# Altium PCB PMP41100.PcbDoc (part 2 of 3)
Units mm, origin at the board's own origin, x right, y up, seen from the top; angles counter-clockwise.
Board outline 49.66 x 37.36 mm, 2 copper layers (Top Layer, Bottom Layer), stack 1.016 mm thick; 100 components, 64 nets, 348 pads, 1132 vias.
Unrouted connection lines stored in the file: 60.
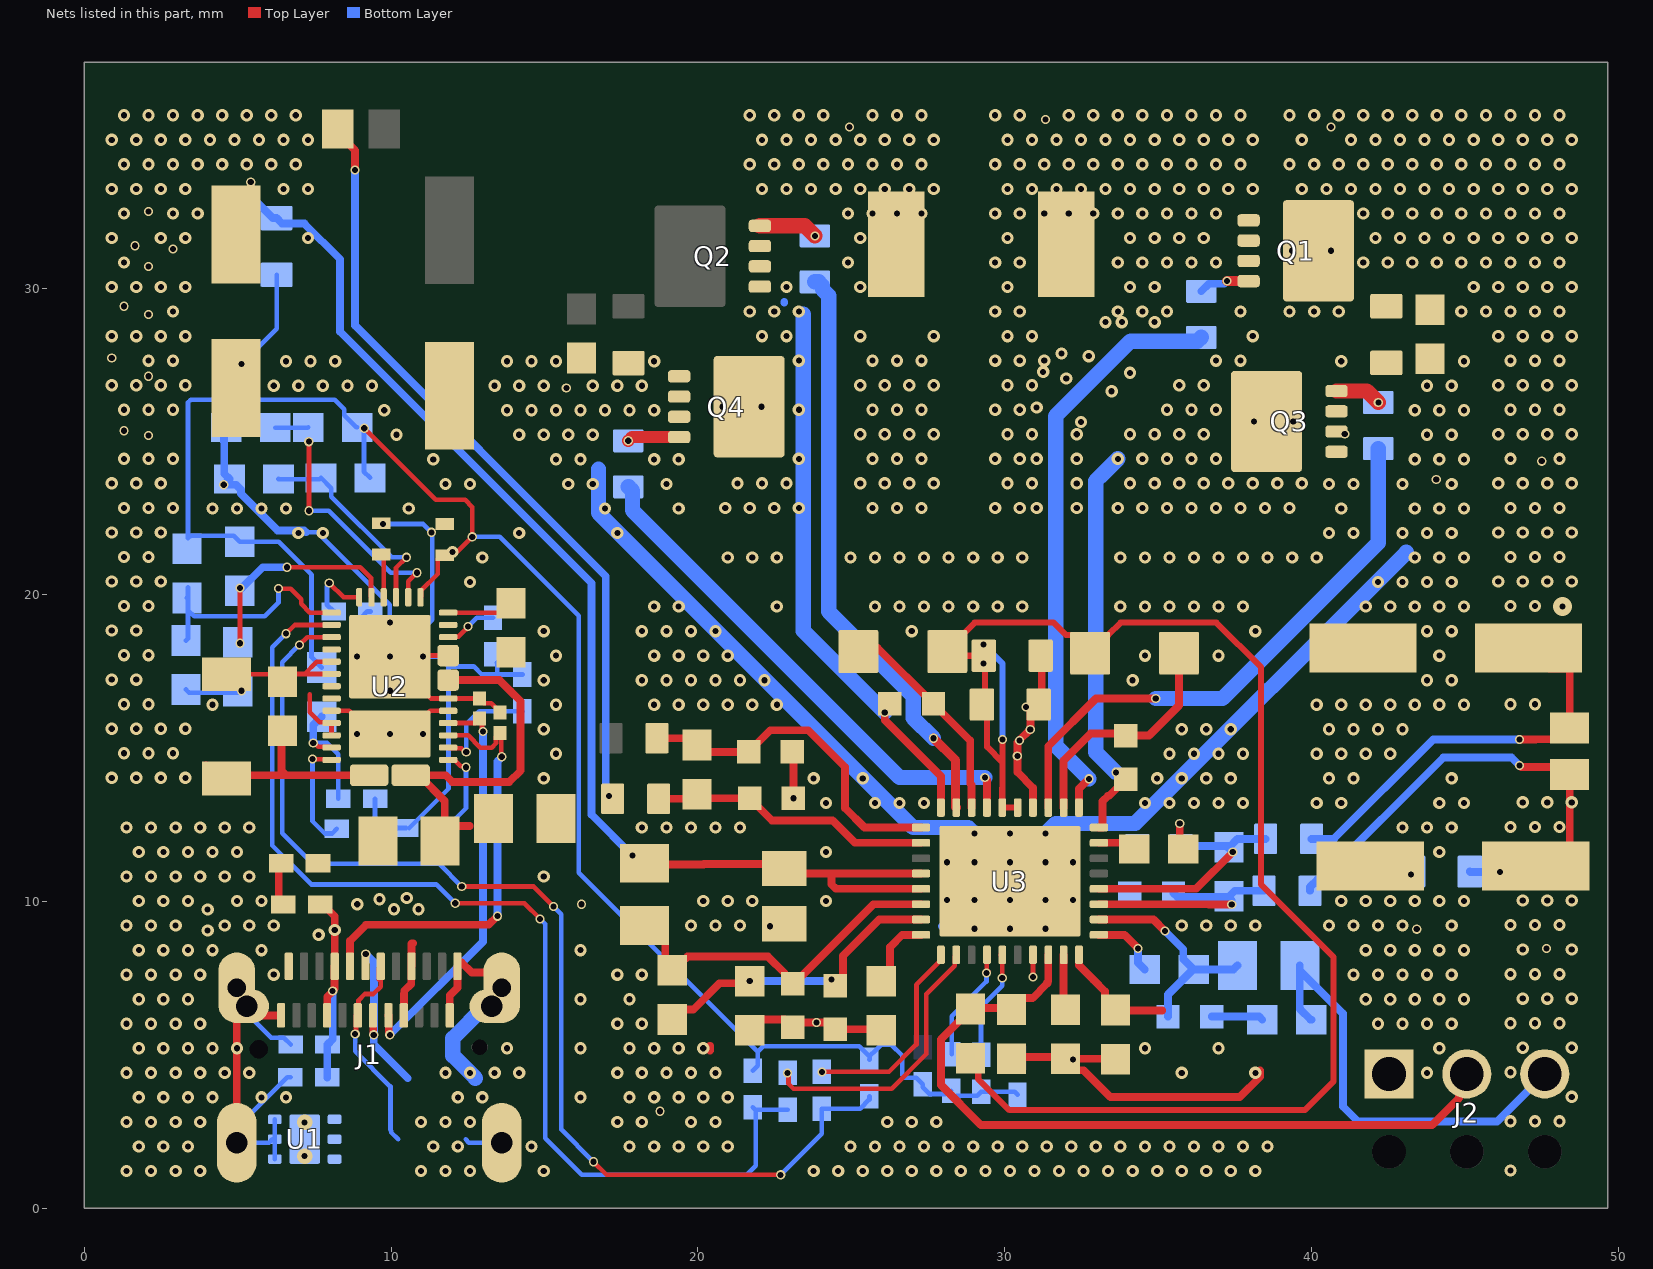
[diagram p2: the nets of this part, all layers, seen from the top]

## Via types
v1: diameter 0.4, hole 0.2, Top Layer to Bottom Layer, 988 vias
v2: diameter 0.3, hole 0.2, Top Layer to Bottom Layer, tented both sides, 103 vias
v3: diameter 0.5, hole 0.2, Top Layer to Bottom Layer, 34 vias
v4: diameter 0.4, hole 0.2, Top Layer to Bottom Layer, tented both sides, 5 vias
v5: diameter 0.4, hole 0.203, Top Layer to Bottom Layer, tented both sides, 1 vias
v6: diameter 0.61, hole 0.203, Top Layer to Bottom Layer, tented both sides, 1 vias

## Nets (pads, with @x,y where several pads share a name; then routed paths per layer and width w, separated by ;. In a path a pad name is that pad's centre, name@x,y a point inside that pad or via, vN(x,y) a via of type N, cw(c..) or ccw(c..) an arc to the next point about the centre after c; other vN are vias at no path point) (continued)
ACN: C13.2 C16.1 R21.1 U3.29 | length 11.2
  Top Layer w0.254: R21.1@18.666,15.327 19.748,15.327 C13.2@19.97,15.105 20.194,14.881 C16.1@21.655,14.881 22.363,15.589 23.594,15.589 24.799,14.383 24.799,13.047 25.43,12.416 U3.29@27.274,12.416
ACOV: C22.1 R31.1 R32.2 U3.35 | length 10.2
  Top Layer w0.254: R31.1@19.162,6.158 19.482,6.478 19.848,6.478 20.706,7.336 21.616,7.336 v2(21.689,7.409) ; v2(24.351,7.457) C22.1@24.351,7.386 ; C22.1@24.479,7.259 C22.1@24.351,7.386 ; U3.35@27.274,9.416 25.911,9.416 24.733,8.238 24.733,7.513 24.606,7.386 C22.1@24.351,7.386
  Bottom Layer w0.254: v2(21.689,7.409) 24.29,7.409 24.339,7.457 v2(24.351,7.457)
ACP: C13.1 C15.1 R20.1 U3.30 | length 9.3
  Top Layer w0.254: R20.1@18.721,13.35 19.815,13.35 C13.1@19.97,13.505 20.105,13.369 C15.1@21.691,13.369 22.412,12.648 24.39,12.648 25.123,11.916 U3.30@27.274,11.916
ACUV: C19.1 R30.1 R31.2 U3.34 | length 13.6
  Top Layer w0.254: R30.1@17.758,8.71 18.149,9.1 R30.1@18.378,9.1 ; U3.34@27.274,9.916 25.724,9.916 23.383,7.575 23.341,7.575 C19.1@23.087,7.321 22.833,7.575 22.833,7.659 22.287,8.206 19.659,8.206 19.584,8.131 19.51,8.131 19.162,7.783 R31.2@19.162,7.758 18.959,7.758 18.933,7.732 R30.1@18.933,8.71 ; R30.1@18.378,9.1 18.543,9.1 R30.1@18.933,8.71 ; R30.1@18.378,9.1 R30.1@18.26,9.218 18.768,8.71 R30.1@18.933,8.71
ADCIN1: R1.1 R5.2 U2.2 | length 8.6
  Top Layer w0.152: v2(7.316,24.994) 7.32,24.99 7.32,22.745 v2(7.324,22.741) ; U2.2@10.557,19.921 10.557,20.437 v2(10.841,20.721)
  Bottom Layer w0.152: R5.2@6.224,25.451 7.282,25.451 R1.1@7.293,25.462 ; v2(7.324,22.741) 7.967,22.741 9.987,20.721 v2(10.841,20.721)
ADCIN2: R2.1 R7.2 U2.3 | length 6.9
  Top Layer w0.152: U2.3@10.157,19.921 10.157,20.879 v2(10.501,21.223)
  Bottom Layer w0.152: R7.2@6.33,23.777 6.34,23.767 7.664,23.767 R2.1@7.712,23.815 8.051,23.476 8.051,23.2 10.028,21.223 v2(10.501,21.223)
ADCIN3: R3.1 R6.2 U2.5 | length 7.1
  Top Layer w0.152: v2(5.072,18.421) v2(5.072,20.223) ; v2(6.601,20.9) 8.993,20.9 9.34,20.553 9.34,19.938 U2.5@9.357,19.921
  Bottom Layer w0.254: v2(5.072,20.223) 5.134,20.223 5.811,20.9 v2(6.601,20.9)
ADCIN4: R4.1 R8.2 U2.7 | length 8
  Top Layer w0.152: v2(6.33,20.204) 6.721,20.204 7.064,19.861 7.064,19.705 7.348,19.421 U2.7@8.057,19.421
  Bottom Layer w0.152: R4.1@3.341,19.9 3.376,19.935 3.376,20.241 R4.1@3.376,19.503 ; v2(6.33,20.204) 6.33,19.752 6.105,19.528 5.88,19.302 3.577,19.302 R4.1@3.376,19.503 ; R8.2@3.376,18.578 R8.2@3.311,18.513 R8.2@3.376,18.578 ; R8.2@3.376,18.578 R4.1@3.376,19.503
BAT: C35.2 C36.1 J2.3 R19.2 R24.1 R33.2 R34.2 | length 29.6
  Top Layer w0.254: v2(46.789,14.432) 46.802,14.432 46.843,14.391 48.168,14.391 48.426,14.133 48.426,11.828 47.753,11.155 C36.1@47.315,11.155
  Bottom Layer w0.254: R34.2@39.625,7.92 R34.2@39.625,7.755 ; R24.1@39.957,10.352 39.957,10.477 40.205,10.725 40.33,10.725 44.298,14.694 46.528,14.694 v2(46.789,14.432) ; R33.2@40.001,6.147 39.976,6.147 39.628,6.495 39.628,6.52 39.625,6.524 R34.2@39.625,7.755 ; C35.2@45.166,10.978 45.182,10.961 v2(46.152,10.961) ; J2.3@47.608,4.382 46.053,2.826 41.527,2.826 41.029,3.324 41.029,6.351 R34.2@39.625,7.755
  other v1: 46.491,1.235 46.491,2.835 47.291,2.835 48.091,2.835 48.491,3.635 46.491,4.435 46.891,5.235 48.491,5.235 46.491,6.035 47.291,6.035 48.091,6.035 46.891,6.835 47.691,6.835 48.491,6.835 46.491,7.635 47.291,7.635 48.091,7.635 46.891,8.435 48.491,8.435 46.491,9.235 47.291,9.235 48.091,9.235 46.891,10.035 47.691,10.035 48.491,10.035 46.491,12.435 47.291,12.435 48.091,12.435 46.891,13.235 47.691,13.235 48.491,13.235
  other v2: 47.664,8.476
BTST1: C20.2 D1.1 U3.26 | length 7.1
  Top Layer w0.254: D1.1@25.232,18.151 25.344,18.263 25.864,18.263 C20.2@27.681,16.446 27.935,16.192 28.878,15.249 28.878,13.85 28.924,13.804 U3.26@28.924,13.066
BTST2: C21.1 D2.1 U3.20 | length 7.8
  Top Layer w0.254: U3.20@31.924,13.066 31.924,14.6 32.803,15.479 33.886,15.479 C21.1@33.953,15.412 33.957,15.416 34.708,15.416 35.685,16.393 D2.1@35.685,18.097
C_CC1: C11.1 J1.A5 U2.28 | length 13.9
  Top Layer w0.152: U2.28@11.857,15.421 12.51,15.421 12.91,15.021 13.281,15.021 13.418,15.158 13.418,15.366 C11.1@13.552,15.5 13.586,15.466 13.586,14.742 v2(13.606,14.722)
  Top Layer w0.254: J1.A5@8.661,8.175 8.661,8.722 9.182,9.243 13.175,9.243 13.457,9.525 v2(13.469,9.525)
  Bottom Layer w0.254: v2@13.469,9.537 13.469,14.572 13.606,14.709 v2(13.606,14.722)
C_CC2: C12.1 J1.B5 U2.29 | length 13.4
  Top Layer w0.152: U2.29@11.857,15.821 12.751,15.821 12.885,15.955 C12.1@12.885,15.964 12.964,15.884 12.964,15.57 v2(12.992,15.541)
  Top Layer w0.254: J1.B5@9.911,6.29 9.919,6.282 9.919,5.706 9.957,5.668 v2(9.957,5.656)
  Bottom Layer w0.254: v2(9.957,5.656) 12.992,8.691 v2(12.992,15.541)
CAP_MIS: R17.2 U2.6 | length 2.2
  Top Layer w0.152: v2(7.983,20.386) 8.447,19.921 U2.6@8.957,19.921
  Bottom Layer w0.152: v2(7.983,20.386) 7.983,20.346 7.907,20.27 7.907,19.677 R17.2@8.124,19.459
DBG_ACC: U2.10
DRAIN: U2.15 U2.30 U2.40 | length 2.9
  Top Layer w0.152: U2.15@8.057,16.221 8.637,16.221 8.882,15.976 v3(8.882,15.461) ; v3(11.032,15.461) 11.032,15.976 11.277,16.221 U2.30@11.857,16.221
  other v3: 9.957,15.461
FAULT_IN: R9.1 R16.2 U2.18 | length 4
  Top Layer w0.152: v2(7.462,15.169) 7.502,15.169 7.626,15.045 8.033,15.045 U2.18@8.057,15.021
  Bottom Layer w0.152: v2(7.462,15.169) 7.909,15.169 8.276,14.802 R16.2@8.276,13.352
  Bottom Layer w0.254: v2(7.462,15.169) 7.462,15.757 R9.1@7.736,16.031
FB: C24.2 R34.1 R35.2 U3.12 | length 7.3
  Top Layer w0.254: U3.12@33.074,9.416 34.852,9.416 v2(35.23,9.037)
  Bottom Layer w0.254: v2@35.239,9.029 35.822,8.445 35.822,8.131 R35.2@36.168,7.785 37.458,7.785 R34.1@37.593,7.92 ; C24.2@35.328,6.252 35.328,6.97 R35.2@36.143,7.785
FBG: R35.1 U3.11 | length 2.2
  Top Layer w0.254: U3.11@33.074,8.916 33.908,8.916 v2(34.348,8.476)
  Bottom Layer w0.254: v2(34.348,8.476) 34.348,8.005 R35.1@34.568,7.785
FSW_SYNC: R40.2 U3.36 | length 2.4
  Top Layer w0.254: R40.2@25.978,7.4 26.267,7.689 26.267,8.518 26.665,8.916 U3.36@27.274,8.916
HIDRV1: R25.2 U3.27 | length 19.1
  Top Layer w0.3: v2(27.681,15.327) 28.401,14.607 28.401,13.089 U3.27@28.424,13.066
  Bottom Layer w0.3: R25.2@23.94,30.204 R25.2@24.065,30.079
  Bottom Layer w0.5: R25.2@23.815,30.204 R25.2@23.94,30.204 ; R25.2@24.065,30.079 24.065,29.954 24.266,29.753 24.266,19.46 27.02,16.705 27.02,15.988 v2(27.681,15.327)
HIDRV2: R22.2 U3.19 | length 19.2
  Top Layer w0.254: U3.19@32.424,13.066 32.424,13.677 v2(32.749,14.002)
  Bottom Layer w0.5: v2(32.749,14.002) 31.665,15.087 31.665,25.828 34.106,28.27 36.288,28.27 R22.2@36.413,28.395
I2C_SCL: R10.2 R43.1 U2.9 | length 37
  Top Layer w0.152: v2(7.009,18.368) 7.262,18.621 U2.9@8.057,18.621 ; v2(12.301,10.491) 14.643,10.491 v2(15.291,9.842) ; v2(16.595,1.518) 17.021,1.092 v2@22.682,1.092
  Bottom Layer w0.152: v2(7.009,18.368) 6.444,17.804 6.444,12.231 7.447,11.229 11.563,11.229 v2(12.301,10.491) ; v2(15.291,9.842) 15.542,9.591 15.542,2.571 v2(16.595,1.518) ; v2(22.699,1.092) 24.043,2.436 R43.1@24.043,3.248 25.29,3.248 25.593,3.551 R10.2@25.593,3.651
I2C_SDA: R11.2 R42.1 U2.8 | length 36.1
  Top Layer w0.152: v2(6.57,18.735) 6.853,19.018 8.055,19.018 U2.8@8.057,19.021 ; v2(12.091,9.944) 14.345,9.944 v2(14.852,9.437)
  Bottom Layer w0.152: v2(6.57,18.735) 6.122,18.287 6.122,11.828 7.39,10.56 11.475,10.56 v2(12.091,9.944) ; v2(14.852,9.437) 15.02,9.27 15.02,2.282 16.209,1.092 21.59,1.092 21.887,1.39 21.887,3.192 R11.2@21.866,3.213 ; R11.2@21.788,3.291 R11.2@21.866,3.213 ; R42.1@22.926,3.213 R11.2@21.866,3.213
ICHG: R45.2 U3.9 | length 1.8
  Top Layer w0.254: U3.9@31.924,8.266 31.924,6.535 R45.2@31.984,6.475
ILIM_HIZ: R44.2 U3.10 | length 3.8
  Top Layer w0.254: U3.10@32.424,8.266 32.424,7.923 32.902,7.445 33.268,7.079 33.268,6.813 R44.2@33.616,6.465 33.628,6.453 35.142,6.453
LDO_1V5: C10.2 U2.4 | length 1.4
  Top Layer w0.152: C10.2@9.676,21.316 9.757,21.235 U2.4@9.757,19.921
LDO_3V3: C9.2 R1.2 R2.2 R3.2 R4.2 R9.2 R10.1 R11.1 R36.2 R37.2 R38.2 R39.2 U2.1 | length 60.5
  Top Layer w0.152: v2(9.125,25.433) 11.459,23.099 12.408,23.099 12.643,22.864 v2(12.643,21.892) 12.152,21.401 11.854,21.401 C9.2@11.746,21.293 11.632,21.293 11.517,21.178 11.517,20.681 10.981,20.145 10.981,19.945 U2.1@10.957,19.921
  Bottom Layer w0.152: R9.2@7.736,17.631 7.405,17.962 7.405,20.656 6.332,21.73 R3.2@5.066,21.73 4.867,21.928 3.463,21.928 3.376,21.841 3.376,26.271 3.465,26.36 8.16,26.36 8.469,26.051 8.469,25.861 8.868,25.462 R1.2@8.893,25.462 ; v2(9.125,25.433) 9.112,25.42 9.112,24.015 R2.2@9.312,23.815 ; v2(12.643,21.892) 13.543,21.892 16.113,19.322 16.113,10.946 21.922,5.137 ; R11.1@21.788,4.491 21.838,4.54 21.949,4.651 21.949,5.111 22.126,5.289 25.255,5.289 25.593,4.951 25.817,5.175 25.975,5.333 26.311,5.333 26.662,4.983 26.662,4.349 26.751,4.26 27.122,4.26 R37.2@27.331,4.05 27.331,3.95 27.555,3.726 28.162,3.726 R38.2@28.264,3.828 ; R10.1@25.593,4.851 25.602,4.86 R10.1@25.602,4.951 ; R38.2@28.228,3.772 28.327,3.673 29.105,3.673 R39.2@29.232,3.8 30.325,3.8 R36.2@30.42,3.704
  other v5: 12.003,21.401
LODRV1: R28.1 U3.25 | length 16.9
  Top Layer w0.254: v2(29.355,14.048) 29.355,14.035 29.424,13.966 U3.25@29.424,13.066
  Bottom Layer w0.5: R28.1@17.728,23.523 17.742,23.523 17.867,23.398 17.867,22.754 26.574,14.048 v2(29.355,14.048)
LODRV2: R29.1 U3.21 | length 18.6
  Top Layer w0.254: U3.21@31.424,13.066 31.424,15.068 32.977,16.621 v2(34.925,16.621)
  Bottom Layer w0.5: v2(34.925,16.621) 37.104,16.621 42.183,21.7 R29.1@42.183,24.771
MODE: R41.2 U3.17 | length 1.2
  Top Layer w0.254: U3.17@33.074,11.916 33.076,11.918 34.019,11.918 R41.2@34.225,11.712
NetC1_1: C1.1 C2.1 C3.1 C4.1 J1.A4 J1.A9 J1.B4 J1.B9 L1.1 U1.4 U1.5 U1.6 | length 9.4
  Top Layer w0.254: C3.1@7.682,9.904 7.782,9.904 8.161,9.525 J1.A4@8.161,7.89 8.153,7.882 8.153,7.155 8.092,7.095 v2(8.092,7.082) 8.092,7.07 7.919,6.896 7.919,6.298 J1.B9@7.911,6.29 ; J1.B4@10.411,6.29 10.416,6.295 10.416,6.983 10.429,6.997 10.429,7.089 10.653,7.313 10.653,7.882 J1.A9@10.668,7.896 ; J1.A9@10.661,7.89 J1.A9@10.668,7.896 ; 10.714,8.644 10.683,8.644 10.668,8.629 J1.A9@10.668,7.896
  Bottom Layer w0.254: C1.1@7.916,4.27 7.916,5.333 C2.1@7.924,5.341 8.092,5.509 v2(8.092,7.082)
  other v1: 10.091,9.752 10.891,9.752
  other v4: 7.636,8.916 8.161,9.076 8.894,9.916 9.621,10.076 10.507,10.114
NetC6_1: C6.1 U2.38 | length 2.2
  Top Layer w0.152: U2.38@11.857,19.421 13.596,19.421 13.79,19.615 C6.1@13.904,19.729
NetC7_1: C7.1 C8.1 U2.20-21-22 | length 7.1
  Top Layer w0.254: C7.1@3.962,14.433 4.385,14.01 C7.1@4.635,14.01 4.746,14.121 6.577,14.121 ; C8.1@6.46,15.565 6.428,15.533 6.428,14.27 6.577,14.121 ; U2.20-21-22@9.281,14.121 6.577,14.121
NetC24_1: C24.1 R33.1 | length 1.7
  Bottom Layer w0.254: C24.1@36.75,6.252 38.297,6.252 R33.1@38.401,6.147
NetQ1_4: Q1.4 R22.1 | length 1.7
  Top Layer w0.32: v2(37.251,30.228) Q1.4@37.953,30.228
  Bottom Layer w0.254: R22.1@36.413,29.895 36.661,30.143 37.154,30.143 37.239,30.228 v2(37.251,30.228)
NetQ2_4: Q2.4 R25.1 | length 1.9
  Top Layer w0.508: Q2.4@22.022,32.031 23.488,32.031 v2(23.815,31.704)
NetQ3_4: Q3.4 R29.2 | length 1.5
  Top Layer w0.254: v2@42.179,26.271 v2(42.183,26.271)
  Top Layer w0.5: Q3.4@40.819,26.644 41.81,26.644 v2(42.183,26.271)
NetQ4_4: Q4.4 R28.2 | length 1.7
  Top Layer w0.4: v2(17.728,25.023) 17.85,25.144 Q4.4@19.389,25.144
NetR42_2: R42.2 U3.2 | length 9
  Top Layer w0.152: v2(22.926,4.413) 22.954,4.385 22.954,4.067 23.118,3.904 26.32,3.904 27.447,5.031 27.447,6.986 28.375,7.914 28.375,8.217 U3.2@28.424,8.266
NetR43_2: R43.2 U3.1 | length 6.7
  Top Layer w0.152: v2(24.043,4.448) 26.23,4.448 27.125,5.343 27.125,7.291 27.924,8.091 U3.1@27.924,8.266
P_OUT: C29.1 C30.2 C32.1 Q1.5 Q1.6 Q1.7 Q1.8 Q1.9@40.233,31.218 R19.1 R23.1 | length 15.1
  Top Layer w0.254: v2(46.784,15.286) 47.315,15.286 47.321,15.293 48.048,15.293 48.426,15.671 C29.1@48.426,17.591 ; C29.1@48.426,17.591 47.754,17.591 C29.1@47.081,18.264 47.753,18.264 C29.1@48.426,17.591
  Bottom Layer w0.254: R23.1@40.007,12.044 40.735,12.044 43.976,15.286 v2(46.784,15.286)
  other v1: 46.491,16.435 47.291,16.435 46.491,19.635 47.291,19.635 46.091,20.435 46.891,20.435 47.691,20.435 48.491,20.435 46.491,21.235 47.291,21.235 48.091,21.235 46.091,22.035 46.891,22.035 47.691,22.035 48.491,22.035 46.491,22.835 47.291,22.835 48.091,22.835 46.091,23.635 46.891,23.635 47.691,23.635 48.491,23.635 46.491,24.435 48.091,24.435 46.091,25.235 46.891,25.235 47.691,25.235 48.491,25.235 46.491,26.035 47.291,26.035 48.091,26.035 46.091,26.835 46.891,26.835 47.691,26.835 48.491,26.835 46.491,27.635 47.291,27.635 48.091,27.635 46.091,28.435 46.891,28.435 47.691,28.435 48.491,28.435 39.291,29.235 40.091,29.235 40.891,29.235 44.891,29.235 45.691,29.235 46.491,29.235 47.291,29.235 48.091,29.235 45.291,30.035 46.091,30.035 46.891,30.035 47.691,30.035 48.491,30.035 41.691,30.835 42.491,30.835 43.291,30.835 44.091,30.835 44.891,30.835 45.691,30.835 46.491,30.835 47.291,30.835 48.091,30.835 42.091,31.635 42.891,31.635 43.691,31.635 44.491,31.635 45.291,31.635 46.091,31.635 46.891,31.635 47.691,31.635 48.491,31.635 41.691,32.435 42.491,32.435 43.291,32.435 44.091,32.435 44.891,32.435 45.691,32.435 46.491,32.435 47.291,32.435 48.091,32.435 39.691,33.235 40.491,33.235 41.291,33.235 42.091,33.235 42.891,33.235 43.691,33.235 44.491,33.235 45.291,33.235 46.091,33.235 46.891,33.235 47.691,33.235 48.491,33.235 39.291,34.035 40.091,34.035 40.891,34.035 41.691,34.035 42.491,34.035 43.291,34.035 44.091,34.035 44.891,34.035 45.691,34.035 46.491,34.035 47.291,34.035 48.091,34.035 39.691,34.835 41.291,34.835 42.091,34.835 42.891,34.835 43.691,34.835 44.491,34.835 45.291,34.835 46.091,34.835 46.891,34.835 47.691,34.835 48.491,34.835 39.291,35.635 40.091,35.635 40.891,35.635 41.691,35.635 42.491,35.635 43.291,35.635 44.091,35.635 44.891,35.635 45.691,35.635 46.491,35.635 47.291,35.635 48.091,35.635
  other v2: 47.511,24.359 40.638,35.255
  other v3: 39.363,31.218 40.638,31.218
  other v6: 48.185,19.618
PGND: C1.2 C2.2 C3.2 C4.2 C5.2 C6.2 C7.2 C8.2 C9.1 C10.1 C11.2 C12.2 C15.2 C16.2 C17.2 C18.2 C19.2 C22.2 C23.2 C25.2 C26.2 C27.2 C28.1 C29.2 C30.1 C31.2 C32.2 C33.2 C34.2 C35.1 C36.2 J1.A1 J1.A12 J1.B1 J1.B12 J1.S1 J1.S2 J1.S3 J1.S4 J2.1 Q3.1 Q3.2 Q3.3 Q4.1 Q4.2 Q4.3 R5.1 R6.1 R7.1 R8.1 R12.1 R13.1 R14.1 R15.1 R16.1 R17.1 R27.1 R32.1 R40.1 R41.1 R44.1 R45.1 U1.1 U1.2 U1.3 U1.7@7.179,2.253 U2.11 U2.12 U2.14 U2.16 U2.17 U2.31 U2.34-35 U2.39 U3.7 U3.22 U3.37 | length 132
  Top Layer w0.152: C7.2@4.635,17.41 6.215,17.41 C8.2@6.46,17.165 6.716,17.421 7.175,17.421 ; 7.348,16.76 7.344,16.756 7.344,16.173 7.672,15.845 8.033,15.845 U2.16@8.057,15.821 U2.17@8.057,15.421 ; U2.12@8.057,17.421 7.175,17.421 ; U2.11@8.057,17.821 7.575,17.821 7.175,17.421 ; v3(9.957,16.876) 11.032,16.876 11.287,16.621 U2.31@11.857,16.621 C12.2@12.885,16.621 ; v3(11.032,17.986) 11.067,18.021 U2.34-35@11.857,18.021 ; C12.2@12.885,16.624 C12.2@12.885,16.621 ; C11.2@13.552,16.16 13.552,16.18 13.262,16.47 13.018,16.47 12.885,16.604 C12.2@12.885,16.621 ; C6.2@13.782,18.021 C6.2@13.783,18.022 ; v2(30.922,7.537) 30.923,7.538 30.923,8.265 U3.7@30.924,8.266
  Top Layer w0.254: J1.S3@4.966,2.14 4.966,6.265 J1.S1@5.291,6.59 5.291,6.571 5.572,6.29 J1.B12@6.411,6.29 ; C4.2@6.415,11.254 6.334,11.173 6.334,10.052 C3.2@6.482,9.904 ; J1.A1@6.661,7.575 J1.A1@6.661,7.89 ; J1.B1@11.911,6.29 11.911,6.939 12.161,7.189 J1.A12@12.161,7.89 ; 12.303,8.01 12.625,7.688 13.169,7.688 13.606,7.251 J1.S2@13.606,7.19 ; 20.394,5.148 20.394,5.299 ; R32.1@21.689,5.809 22.037,6.157 22.687,6.157 22.692,6.152 22.833,6.152 C19.2@23.087,5.898 ; C16.2@23.078,14.881 23.113,14.845 v2(23.113,13.369) ; C19.2@23.118,5.868 23.309,6.06 v2(23.87,6.06) 24.255,6.06 C22.2@24.479,5.836 25.943,5.836 R40.1@25.978,5.8 ; R27.1@30.225,4.88 30.281,4.936 31.923,4.936 R45.1@31.984,4.875 R45.1@32.2,4.875 ; v2(30.695,16.345) 31.03,16.345 C26.2@31.109,16.424 ; U3.22@30.924,13.066 30.922,13.068 30.922,13.714 30.423,14.214 30.423,14.734 v2(30.414,14.743) 30.423,14.752 30.423,15.185 30.481,15.243 v2(30.481,15.256) v2(30.837,15.613) 30.846,15.622 30.846,16.162 C26.2@31.109,16.424 ; C23.2@31.172,18.016 31.21,17.978 31.21,16.471 31.153,16.415 31.119,16.415 C26.2@31.109,16.424 ; R44.1@33.616,4.865 33.606,4.875 R45.1@32.2,4.875 ; v2(35.708,12.546) 35.708,11.829 R41.1@35.825,11.712 ; v1@38.33,4.491 38.33,4.291 37.666,3.627 33.447,3.627 32.573,4.502 32.332,4.502 32.224,4.61 v2(32.224,4.851) R45.1@32.2,4.875
  Top Layer w1: J1.S1@4.966,6.64 J1.S1@4.966,7.19
  Bottom Layer w0.152: R8.1@3.311,16.913 3.41,16.813 R6.1@5.093,16.813 ; J1.S1@4.966,7.19 4.966,6.682 6.083,5.565 6.501,5.565 C2.2@6.724,5.341 ; v2(5.124,27.531) 6.265,28.672 C34.2@6.265,30.435 ; U1.1@6.204,1.603 U1.2@6.204,2.253 ; U1.3@6.204,2.903 U1.2@6.204,2.253 ; C1.2@6.716,4.27 6.616,4.27 4.966,2.62 J1.S3@4.966,2.14 6.017,2.14 6.129,2.253 U1.2@6.204,2.253 ; 7.221,22.039 7.595,22.039 9.957,19.677 v3(9.957,19.096) 11.249,19.096 11.339,19.185 11.339,22.012 11.042,22.309 v2(9.728,22.309) ; v3(8.882,17.986) 8.882,18.08 9.001,18.198 9.001,19.235 9.224,19.459 R17.1@9.324,19.459 ; R15.1@9.431,12.376 R15.1@9.454,12.399 ; R16.1@9.476,13.352 9.476,12.421 R15.1@9.454,12.399 ; R12.1@10.493,12.399 R15.1@9.454,12.399 ; R12.1@10.593,12.399 11.869,13.675 11.869,17.667 ; v3(11.032,17.986) 11.55,17.986 11.869,17.667 ; 12.428,2.248 12.537,2.14 J1.S4@13.606,2.14 ; 13.445,17.403 12.953,17.403 12.69,17.667 11.869,17.667 ; R13.1@13.445,17.788 13.457,17.776 13.457,17.403 R14.1@14.279,17.403
  Bottom Layer w0.254: R5.1@4.624,25.451 4.553,25.379 4.553,25.003 4.561,24.995 4.561,23.945 R7.1@4.73,23.777 v2(4.54,23.588) 4.944,23.588 5.103,23.429 5.103,23.294 6.293,22.103 7.156,22.103 7.221,22.039 ; J1.S2@13.587,7.21 J1.S2@13.606,7.19 ; J1.S4@13.777,1.435 J1.S4@13.777,2.896 ; 27.958,9.196 28.039,9.116 v3(29.014,9.116) ; 30.985,9.54 30.985,9.508 31.334,9.158 v3(31.334,9.116)
  Bottom Layer w0.5: J1.S1@4.966,7.19 J1.S1@4.966,7.816 ; 12.744,4.243 12.011,4.976 12.011,5.545 13.056,6.59 J1.S2@13.281,6.59 ; 16.761,24.106 16.761,22.675 27.02,12.416 28.814,12.416 v3(29.014,12.216) ; v3(31.334,12.216) 31.665,12.546 34.257,12.546 43.098,21.387
  other v1: 1.373,1.218 2.173,1.218 2.973,1.218 3.773,1.218 10.973,1.218 11.773,1.218 12.573,1.218 14.973,1.218 23.773,1.218 24.573,1.218 25.373,1.218 26.173,1.218 26.973,1.218 27.773,1.218 28.573,1.218 29.373,1.218 30.173,1.218 30.973,1.218 31.773,1.218 32.573,1.218 33.373,1.218 34.173,1.218 34.973,1.218 35.773,1.218 36.573,1.218 37.373,1.218 38.173,1.218 1.773,2.018 2.573,2.018 3.373,2.018 11.373,2.018 12.173,2.018 14.573,2.018 17.773,2.018 18.573,2.018 19.373,2.018 20.173,2.018 20.973,2.018 24.973,2.018 25.773,2.018 26.573,2.018 27.373,2.018 28.173,2.018 28.973,2.018 29.773,2.018 30.573,2.018 31.373,2.018 32.173,2.018 32.973,2.018 33.773,2.018 34.573,2.018 35.373,2.018 36.173,2.018 36.973,2.018 37.773,2.018 38.573,2.018 1.373,2.818 2.173,2.818 2.973,2.818 3.773,2.818 10.973,2.818 11.773,2.818 12.573,2.818 17.373,2.818 18.173,2.818 19.773,2.818 20.573,2.818 26.173,2.818 26.973,2.818 27.773,2.818 1.773,3.618 2.573,3.618 3.373,3.618 4.173,3.618 5.773,3.618 6.573,3.618 12.173,3.618 12.973,3.618 16.173,3.618 17.773,3.618 18.573,3.618 19.373,3.618 20.173,3.618 20.973,3.618 1.373,4.418 2.173,4.418 2.973,4.418 3.773,4.418 4.573,4.418 5.373,4.418 11.773,4.418 12.573,4.418 13.373,4.418 14.173,4.418 17.373,4.418 18.173,4.418 18.973,4.418 19.773,4.418 20.573,4.418 35.773,4.418 38.173,4.418 43.773,4.418 1.773,5.218 2.573,5.218 3.373,5.218 4.173,5.218 4.973,5.218 13.773,5.218 16.173,5.218 17.773,5.218 18.573,5.218 19.373,5.218 20.173,5.218 34.573,5.218 36.973,5.218 44.173,5.218 1.373,6.018 2.173,6.018 2.973,6.018 3.773,6.018 17.373,6.018 18.173,6.018 42.173,6.018 42.973,6.018 43.773,6.018 44.573,6.018 1.773,6.818 2.573,6.818 3.373,6.818 16.173,6.818 17.773,6.818 41.773,6.818 42.573,6.818 43.373,6.818 44.173,6.818 44.973,6.818 1.373,7.618 2.173,7.618 2.973,7.618 3.773,7.618 6.173,7.618 17.373,7.618 18.173,7.618 41.373,7.618 42.173,7.618 42.973,7.618 43.773,7.618 44.573,7.618 1.773,8.418 2.573,8.418 3.373,8.418 4.173,8.418 5.773,8.418 16.173,8.418 41.773,8.418 42.573,8.418 43.373,8.418 44.173,8.418 44.973,8.418 4.018,9.056 1.373,9.218 2.173,9.218 2.973,9.218 4.573,9.218 5.373,9.218 6.173,9.218 19.773,9.218 20.573,9.218 21.373,9.218 35.773,9.218 36.573,9.218 37.373,9.218 38.173,9.218 40.573,9.218 41.373,9.218 42.173,9.218 42.973,9.218 44.573,9.218 4.017,9.739 1.773,10.018 2.573,10.018 3.373,10.018 4.973,10.018 5.773,10.018 20.173,10.018 20.973,10.018 21.773,10.018 24.173,10.018 40.973,10.018 41.773,10.018 42.573,10.018 43.373,10.018 44.173,10.018 44.973,10.018 1.373,10.818 2.173,10.818 2.973,10.818 3.773,10.818 4.573,10.818 5.373,10.818 14.973,10.818 1.773,11.618 2.573,11.618 3.373,11.618 4.173,11.618 4.973,11.618 24.173,11.618 44.173,11.618 1.373,12.418 2.173,12.418 2.973,12.418 3.773,12.418 4.573,12.418 5.373,12.418 18.173,12.418 18.973,12.418 19.773,12.418 20.573,12.418 21.373,12.418 42.973,12.418 43.773,12.418 44.573,12.418 24.173,13.218 25.773,13.218 26.573,13.218 27.373,13.218 34.573,13.218 35.373,13.218 36.173,13.218 36.973,13.218 37.773,13.218 40.173,13.218 40.973,13.218 44.173,13.218 44.973,13.218 14.973,14.018 23.773,14.018 25.373,14.018 34.973,14.018 35.773,14.018 36.573,14.018 37.373,14.018 40.573,14.018 41.373,14.018 44.573,14.018 15.373,14.818 35.373,14.818 36.173,14.818 36.973,14.818 37.773,14.818 40.173,14.818 40.973,14.818 41.773,14.818 42.573,14.818 14.973,15.618 35.773,15.618 36.573,15.618 37.373,15.618 40.573,15.618 41.373,15.618 42.173,15.618 42.973,15.618 4.173,16.418 15.373,16.418 18.573,16.418 19.373,16.418 20.173,16.418 20.973,16.418 21.773,16.418 22.573,16.418 40.173,16.418 40.973,16.418 41.773,16.418 42.573,16.418 43.373,16.418 44.173,16.418 44.973,16.418 14.973,17.218 18.173,17.218 18.973,17.218 19.773,17.218 20.573,17.218 21.373,17.218 22.173,17.218 34.173,17.218 43.773,17.218 44.573,17.218 15.373,18.018 18.573,18.018 19.373,18.018 20.173,18.018 20.973,18.018 34.573,18.018 36.973,18.018 44.173,18.018 14.973,18.818 18.173,18.818 18.973,18.818 19.773,18.818 20.573,18.818 26.973,18.818 38.173,18.818 43.773,18.818 44.573,18.818 18.573,19.618 19.373,19.618 22.573,19.618 25.773,19.618 26.573,19.618 27.373,19.618 28.173,19.618 28.973,19.618 29.773,19.618 30.573,19.618 33.773,19.618 34.573,19.618 35.373,19.618 36.173,19.618 36.973,19.618 37.773,19.618 41.773,19.618 42.573,19.618 43.373,19.618 44.173,19.618 44.973,19.618 12.573,20.418 42.173,20.418 42.973,20.418 43.773,20.418 44.573,20.418 12.973,21.218 20.973,21.218 21.773,21.218 22.573,21.218 24.973,21.218 25.773,21.218 26.573,21.218 27.373,21.218 28.173,21.218 28.973,21.218 29.773,21.218 30.573,21.218 33.773,21.218 34.573,21.218 35.373,21.218 36.173,21.218 36.973,21.218 37.773,21.218 38.573,21.218 39.373,21.218 40.173,21.218 43.373,21.218 44.173,21.218 44.973,21.218 6.973,22.018 7.773,22.018 14.173,22.018 17.373,22.018 40.573,22.018 41.373,22.018 42.973,22.018 43.773,22.018 44.573,22.018 4.173,22.818 4.973,22.818 5.773,22.818 6.573,22.818 10.573,22.818 16.973,22.818 19.373,22.818 40.973,22.818 43.373,22.818 44.173,22.818 44.973,22.818 11.773,23.618 12.573,23.618 15.773,23.618 16.573,23.618 18.973,23.618 40.573,23.618 41.373,23.618 42.973,23.618 44.573,23.618 11.373,24.418 15.373,24.418 16.173,24.418 18.573,24.418 19.373,24.418 43.373,24.418 44.173,24.418 44.973,24.418 10.173,25.218 14.173,25.218 14.973,25.218 15.773,25.218 16.573,25.218 43.773,25.218 44.573,25.218 9.773,26.018 13.773,26.018 14.573,26.018 15.373,26.018 16.173,26.018 16.973,26.018 17.773,26.018 18.573,26.018 43.373,26.018 44.173,26.018 44.973,26.018 6.173,26.818 6.973,26.818 7.773,26.818 8.573,26.818 9.373,26.818 13.373,26.818 14.173,26.818 14.973,26.818 16.573,26.818 17.373,26.818 18.173,26.818 43.773,26.818 44.573,26.818 6.573,27.618 7.373,27.618 8.173,27.618 13.773,27.618 14.573,27.618 15.373,27.618 18.573,27.618 40.973,27.618 44.973,27.618
  other v2: 18.768,3.166 43.434,9.101 22.352,9.196 16.201,9.916 43.249,10.889 5.124,16.876 11.312,22.039 44.07,23.763 41.088,25.244 15.711,26.744
  other v3: 7.179,1.703 7.179,2.803 30.174,9.116 28.124,10.051 29.014,10.051 30.174,10.051 31.334,10.051 32.224,10.051 28.124,11.281 29.014,11.281 30.174,11.281 31.334,11.281 32.224,11.281 30.174,12.216 9.957,17.986
PIN26_RESV: R12.2 U2.26 | length 3
  Top Layer w0.152: U2.26@11.857,14.621 12.057,14.621 12.27,14.408 12.412,14.408 v2(12.44,14.38)
  Bottom Layer w0.152: R12.2@11.693,12.399 11.793,12.399 12.44,13.046 v2(12.44,14.38)
PIN27_RESV: R14.2 U2.27 | length 3.6
  Top Layer w0.152: U2.27@11.857,15.021 11.881,14.997 12.291,14.997 12.408,14.88 v2(12.448,14.88)
  Bottom Layer w0.152: v2(12.448,14.88) 12.448,15.778 12.873,16.203 R14.2@14.279,16.203
PIN36_RESV: R13.2 U2.36 | length 1.8
  Top Layer w0.152: U2.36@11.857,18.621 11.881,18.645 12.081,18.645 12.2,18.645 v2@12.479,18.924 ; v2@12.479,18.881 v2@12.479,18.924 ; v2@12.479,18.924 12.507,18.952 v2(12.507,18.971) 12.479,18.943 v2@12.479,18.924
  Bottom Layer w0.152: v2(12.507,18.971) 12.507,18.973 12.793,19.258 R13.2@13.321,19.258
PLUG_EVENT: U2.37
PLUG_FLIP: U2.13
PPHV: C25.1 C33.1 C34.1 R18.1 R20.2 R30.2 U3.32 U3.33 | length 67.5
  Top Layer w0.254: C33.1@4.936,31.749 5.423,32.236 v2(5.423,33.455) ; R18.1@8.254,35.185 8.254,35.06 8.825,34.489 v2(8.825,33.848) ; R30.2@18.26,11.374 R30.2@18.26,11.25 R30.2@18.344,11.25 ; R30.2@18.465,11.213 20.183,11.213 20.196,11.226 22.355,11.226 22.579,11.003 22.658,11.082 C25.1@22.816,11.082 22.982,10.916 24.353,10.916 ; U3.33@27.274,10.416 27.272,10.418 24.502,10.418 24.353,10.566 24.353,10.916 ; U3.32@27.274,10.916 24.353,10.916
  Bottom Layer w0.254: v2(5.423,33.455) 5.432,33.446 5.432,32.993 6.14,32.285 C34.1@6.265,32.285 6.445,32.105 7.171,32.105 8.336,30.94 8.336,28.575 16.535,20.376 16.535,12.832 v2(17.867,11.5) ; v2(8.825,33.848) 8.825,28.78 16.997,20.608 16.997,13.551 17.098,13.45 v2(17.098,13.438)
  other v1: 0.891,14.035 1.691,14.035 2.491,14.035 3.291,14.035 1.291,14.835 2.091,14.835 2.891,14.835 0.891,15.635 1.691,15.635 2.491,15.635 3.291,15.635 1.291,16.435 2.091,16.435 0.891,17.235 1.691,17.235 1.291,18.035 2.091,18.035 0.891,18.835 1.691,18.835 1.291,19.635 2.091,19.635 0.891,20.435 1.691,20.435 2.491,20.435 1.291,21.235 2.091,21.235 0.891,22.035 1.691,22.035 2.491,22.035 1.291,22.835 2.091,22.835 2.891,22.835 0.891,23.635 1.691,23.635 2.491,23.635 1.291,24.435 2.091,24.435 2.891,24.435 1.291,26.035 2.091,26.035 2.891,26.035 0.891,26.835 1.691,26.835 2.491,26.835 3.291,26.835 2.091,27.635 2.891,27.635 0.891,28.435 1.691,28.435 2.491,28.435 3.291,28.435 2.891,29.235 0.891,30.035 1.691,30.035 2.491,30.035 3.291,30.035 1.291,30.835 0.891,31.635 2.491,31.635 3.291,31.635 7.291,31.635 1.291,32.435 2.891,32.435 3.691,32.435 0.891,33.235 1.691,33.235 2.491,33.235 3.291,33.235 6.491,33.235 7.291,33.235 1.291,34.035 2.091,34.035 2.891,34.035 3.691,34.035 4.491,34.035 5.291,34.035 6.091,34.035 6.891,34.035 0.891,34.835 1.691,34.835 2.491,34.835 3.291,34.835 4.091,34.835 4.891,34.835 5.691,34.835 6.491,34.835 7.291,34.835 1.291,35.635 2.091,35.635 2.891,35.635 3.691,35.635 4.491,35.635 5.291,35.635 6.091,35.635 6.891,35.635
  other v2: 2.091,25.197 1.291,25.349 2.091,27.125 0.891,27.72 2.091,29.14 1.291,29.408 2.091,30.71 2.891,31.272 1.653,31.383 2.091,32.499
REGN: C23.1 C26.1 D1.2 D2.2 R26.2 U3.23 U3.24 | length 51.1
  Top Layer w0.2: R26.2@28.888,4.898 29.14,4.647 29.14,4.215 30.155,3.2 39.785,3.2 40.725,4.14 40.725,8.189 38.362,10.552 38.362,17.639 36.904,19.097 33.785,19.097 33.385,18.697 33.335,18.697 D2.2@32.785,18.147 ; C26.1@29.259,16.424 29.427,16.256 29.427,15.043 29.924,14.546 ; v2(29.307,17.767) 29.36,17.714 C26.1@29.36,16.489 ; C23.1@29.322,18.016 28.268,18.016 D1.2@28.132,18.151 28.132,18.201 29.027,19.097 31.599,19.097 31.999,18.697 32.235,18.697 D2.2@32.785,18.147 ; U3.24@29.924,13.066 29.924,13.704 ; U3.24@29.927,13.066 U3.23@30.424,13.066 ; 29.927,13.704 v2(29.927,15.285) ; D2.2@32.785,18.097 D2.2@32.785,18.147
  Bottom Layer w0.2: v2(29.307,17.767) v2(29.307,18.385) 29.927,17.765 v2(29.927,15.285)
SINK_EN: R15.2 U2.19 | length 3.7
  Top Layer w0.152: v2(7.435,14.653) 7.451,14.637 8.041,14.637 U2.19@8.057,14.621
  Bottom Layer w0.152: v2(7.435,14.653) 7.435,12.615 7.831,12.219 8.074,12.219 R15.2@8.231,12.376
SRN: C14.2 C18.1 R24.2 U3.13 | length 8.1
  Top Layer w0.254: U3.13@33.074,9.916 36.649,9.916 36.658,9.906 v2(37.407,9.906)
  Bottom Layer w0.254: C14.2@37.319,10.171 37.5,10.352 R24.2@38.457,10.352 ; v2(37.407,9.906) 37.407,10.047 37.306,10.148 C18.1@35.64,10.148 ; C18.1@35.506,10.282 C18.1@35.64,10.148 ; C18.1@35.506,10.282 C18.1@35.64,10.148 ; C18.1@35.506,10.282 C18.1@35.64,10.148
SRP: C14.1 C17.1 R23.2 U3.14 | length 7.9
  Top Layer w0.254: U3.14@33.074,10.416 33.076,10.418 36.24,10.418 v2(37.436,11.613)
  Bottom Layer w0.254: C17.1@35.749,11.815 37.275,11.815 C14.1@37.319,11.771 37.592,12.044 R23.2@38.507,12.044 ; C14.1@37.298,11.751 37.356,11.692 v2(37.436,11.613)
STAT1: R38.1 U3.4 | length 3.7
  Top Layer w0.152: v2(29.406,7.671) 29.415,7.68 29.415,7.693 29.415,8.257 U3.4@29.422,8.264
  Top Layer w0.254: v2(29.406,7.671) 29.406,7.684 29.415,7.693 v2@29.422,7.699 ; U3.4@29.422,8.264 U3.4@29.424,8.266
  Bottom Layer w0.152: R38.1@28.273,5.028 28.273,6.262 29.406,7.395 v2(29.406,7.671)
STAT2: R39.1 U3.5 | length 3.6
  Top Layer w0.152: v2(29.922,7.512) 29.923,7.513 29.923,8.263 U3.5@29.922,8.264
  Top Layer w0.254: U3.5@29.922,8.264 U3.5@29.924,8.266
  Bottom Layer w0.152: R39.1@29.232,5 29.232,6.573 29.922,7.263 v2(29.922,7.512)
SW1: C20.1 L2.1 Q2.1 Q2.2 Q2.3 Q4.5 Q4.6 Q4.7 Q4.8 Q4.9@21.669,26.135 U3.28 | length 18.3
  Top Layer w0.254: C20.1@26.258,16.446 26.094,16.281 26.094,15.918 27.924,14.088 U3.28@27.924,13.066
  Bottom Layer w0.254: 22.816,29.523 22.816,29.545
  Bottom Layer w0.5: v1@23.439,29.15 23.439,18.821 v2(26.094,16.167)
  other v1: 20.891,22.835 21.691,22.835 22.491,22.835 23.291,22.835 25.691,22.835 26.491,22.835 27.291,22.835 21.291,23.635 22.091,23.635 22.891,23.635 25.291,23.635 26.091,23.635 26.891,23.635 27.691,23.635 23.291,24.435 25.691,24.435 26.491,24.435 27.291,24.435 25.291,25.235 26.091,25.235 26.891,25.235 27.691,25.235 23.291,26.035 25.691,26.035 26.491,26.035 27.291,26.035 25.291,26.835 26.091,26.835 26.891,26.835 27.691,26.835 23.291,27.635 25.691,27.635 26.491,27.635 27.291,27.635 22.091,28.435 22.891,28.435 25.291,28.435 27.691,28.435 21.691,29.235 22.491,29.235 23.291,29.235 22.891,30.035 25.291,30.035 24.891,30.835 25.291,31.635 24.891,32.435 25.691,32.435 26.491,32.435 27.291,32.435 22.091,33.235 22.891,33.235 23.691,33.235 24.491,33.235 25.291,33.235 26.091,33.235 26.891,33.235 27.691,33.235 21.691,34.035 22.491,34.035 23.291,34.035 24.091,34.035 24.891,34.035 25.691,34.035 26.491,34.035 27.291,34.035 22.091,34.835 22.891,34.835 23.691,34.835 24.491,34.835 25.291,34.835 26.091,34.835 26.891,34.835 27.691,34.835 21.691,35.635 22.491,35.635 23.291,35.635 24.091,35.635 25.691,35.635 26.491,35.635 27.291,35.635
  other v2: 24.943,35.255
  other v3: 20.799,26.135 22.074,26.135
SW2: C21.2 L2.2 Q1.1 Q1.2 Q1.3 Q3.5 Q3.6 Q3.7 Q3.8 Q3.9@38.539,25.654 U3.18 | length 13.2
  Top Layer w0.254: U3.18@33.074,12.416 33.191,12.416 33.193,12.418 33.193,13.269 33.373,13.448 33.412,13.448 C21.2@33.953,13.989 33.728,14.214 v2(33.628,14.214)
  Bottom Layer w0.5: 32.968,22.538 32.968,23.712 33.107,23.851
  Bottom Layer w0.508: 32.968,22.538 32.968,14.874 v2(33.628,14.214) ; 33.107,23.851 v1(33.691,24.435)
  other v1: 29.691,22.835 30.491,22.835 31.045,22.835 32.35,22.835 33.691,22.835 34.491,22.835 35.291,22.835 36.091,22.835 36.891,22.835 37.691,22.835 38.491,22.835 39.291,22.835 30.091,23.635 30.891,23.635 32.35,23.635 34.091,23.635 34.891,23.635 35.691,23.635 36.491,23.635 37.291,23.635 38.091,23.635 38.891,23.635 39.691,23.635 29.691,24.435 30.491,24.435 31.045,24.435 32.35,24.435 34.491,24.435 35.291,24.435 36.091,24.435 36.891,24.435 30.091,25.235 30.891,25.235 32.35,25.235 34.091,25.235 34.891,25.235 35.691,25.235 36.491,25.235 32.489,25.638 29.691,26.035 30.491,26.035 35.291,26.035 36.091,26.035 36.891,26.035 31.045,26.111 33.489,26.638 30.091,26.835 30.891,26.835 35.691,26.835 36.491,26.835 32.01,27.051 34.089,27.238 31.256,27.271 29.691,27.635 30.491,27.635 31.291,27.635 36.891,27.635 37.691,27.635 32.743,27.783 31.856,27.871 30.091,28.435 30.891,28.435 38.091,28.435 33.291,28.89 33.823,28.89 34.891,28.89 29.691,29.235 30.491,29.235 33.691,29.235 34.491,29.235 35.291,29.235 37.691,29.235 30.091,30.035 34.091,30.035 34.891,30.035 29.691,30.835 30.491,30.835 33.691,30.835 34.491,30.835 35.291,30.835 36.091,30.835 36.891,30.835 30.091,31.635 34.091,31.635 34.891,31.635 35.691,31.635 36.491,31.635 29.691,32.435 30.491,32.435 31.291,32.435 32.091,32.435 32.891,32.435 33.691,32.435 34.491,32.435 35.291,32.435 36.091,32.435 36.891,32.435 30.091,33.235 30.891,33.235 31.691,33.235 32.491,33.235 33.291,33.235 34.091,33.235 34.891,33.235 35.691,33.235 36.491,33.235 37.291,33.235 38.091,33.235 29.691,34.035 30.491,34.035 31.291,34.035 32.091,34.035 32.891,34.035 33.691,34.035 34.491,34.035 35.291,34.035 36.091,34.035 36.891,34.035 37.691,34.035 30.091,34.835 30.891,34.835 31.691,34.835 32.491,34.835 33.291,34.835 34.091,34.835 34.891,34.835 35.691,34.835 36.491,34.835 37.291,34.835 38.091,34.835 29.691,35.635 30.491,35.635 32.091,35.635 32.891,35.635 33.691,35.635 34.491,35.635 35.291,35.635 36.091,35.635 36.891,35.635 37.691,35.635
  other v2: 31.334,35.498
  other v3: 38.134,25.654 39.409,25.654
TS: J2.2 R26.1 R27.2 U3.8 | length 25.1
  Top Layer w0.254: R27.2@30.225,6.48 30.17,6.536 28.926,6.536 R26.1@28.888,6.498 28.888,6.473 27.924,5.509 27.924,4.02 29.226,2.718 43.936,2.718 44.811,3.593 44.811,4.124 J2.2@45.068,4.382 ; R27.2@30.407,6.688 30.573,6.853 30.913,6.853 31.379,7.32 31.379,7.346 31.388,7.355 ; 31.399,7.34 31.396,7.343 31.396,7.376 31.424,7.404 U3.8@31.424,8.266
USB_N: J1.A7 J1.B7 | length 7.2
  Top Layer w0.152: v2(8.826,5.685) 8.854,5.713 J1.B7@8.854,6.29 ; J1.B7@8.911,6.349 J1.B7@8.911,6.29 8.937,6.316 8.937,6.788 9.136,6.988 9.418,6.988 9.661,7.231 J1.A7@9.661,7.89 9.602,7.831 J1.A7@9.602,7.454
  Bottom Layer w0.152: v2(8.826,5.685) 8.826,5.122 9.977,3.971 9.977,2.561 10.005,2.534 10.005,2.472 10.228,2.248
USB_P: J1.A6 J1.B6 | length 5.7
  Top Layer w0.2: J1.A6@9.161,7.89 9.166,7.895 9.166,8.285 v2(9.171,8.29)
  Top Layer w0.254: J1.B6@9.411,6.29 9.419,6.282 9.419,5.682 9.433,5.668 v2(9.433,5.656)
  Bottom Layer w0.254: v2(9.171,8.29) 9.442,8.02 9.442,5.656 9.433,5.647 9.433,5.355 10.544,4.243
VBUS: C5.1 L1.2 U2.23-24-25 U2.32-33 | length 12.3
  Top Layer w0.254: U2.23-24-25@10.634,14.121 10.809,14.121 U2.23-24-25@10.91,14.121 ; L1.2@11.596,11.974 L1.2@11.749,12.127 ; U2.32-33@11.857,17.221 13.531,17.221 13.89,16.862 13.892,16.862 14.219,16.535 14.219,14.27 13.853,13.903 11.994,13.903 11.776,14.121 U2.23-24-25@10.91,14.121 ; 12.565,12.466 12.088,12.466 L1.2@11.749,12.127 ; U2.23-24-25@10.91,14.121 11.749,13.282 L1.2@11.749,12.127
